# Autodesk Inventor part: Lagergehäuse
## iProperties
Shininess: 20.0
Angle Display Precision: 2
Document Length Units: 11269
Document Angle Units: 11279
Document Time Units: 11290
Document Mass Units: 11283
Document Length Units Precision: 3
Document Angle Units Precision: 2
Created: 2003-02
Part Number: Lagergehäuse
Material: S275JR
Document SubType Name: Modellieren
Designer: Administrator
Density: 0.0
Volumn: 0.0
Area: 0.0
PropertySet Name: Model Information
Control State: 0
Master: False
Checked Out: False
Author: Administrator
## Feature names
1. Grundkörper [Revolution]
2. Fase1 [Chamfer]
3. Senkungen [Hole]
4. Gewindebohrungen [Hole]
5. Rundung1 [Fillet]
6. Lüftungsbohrung [Hole]
